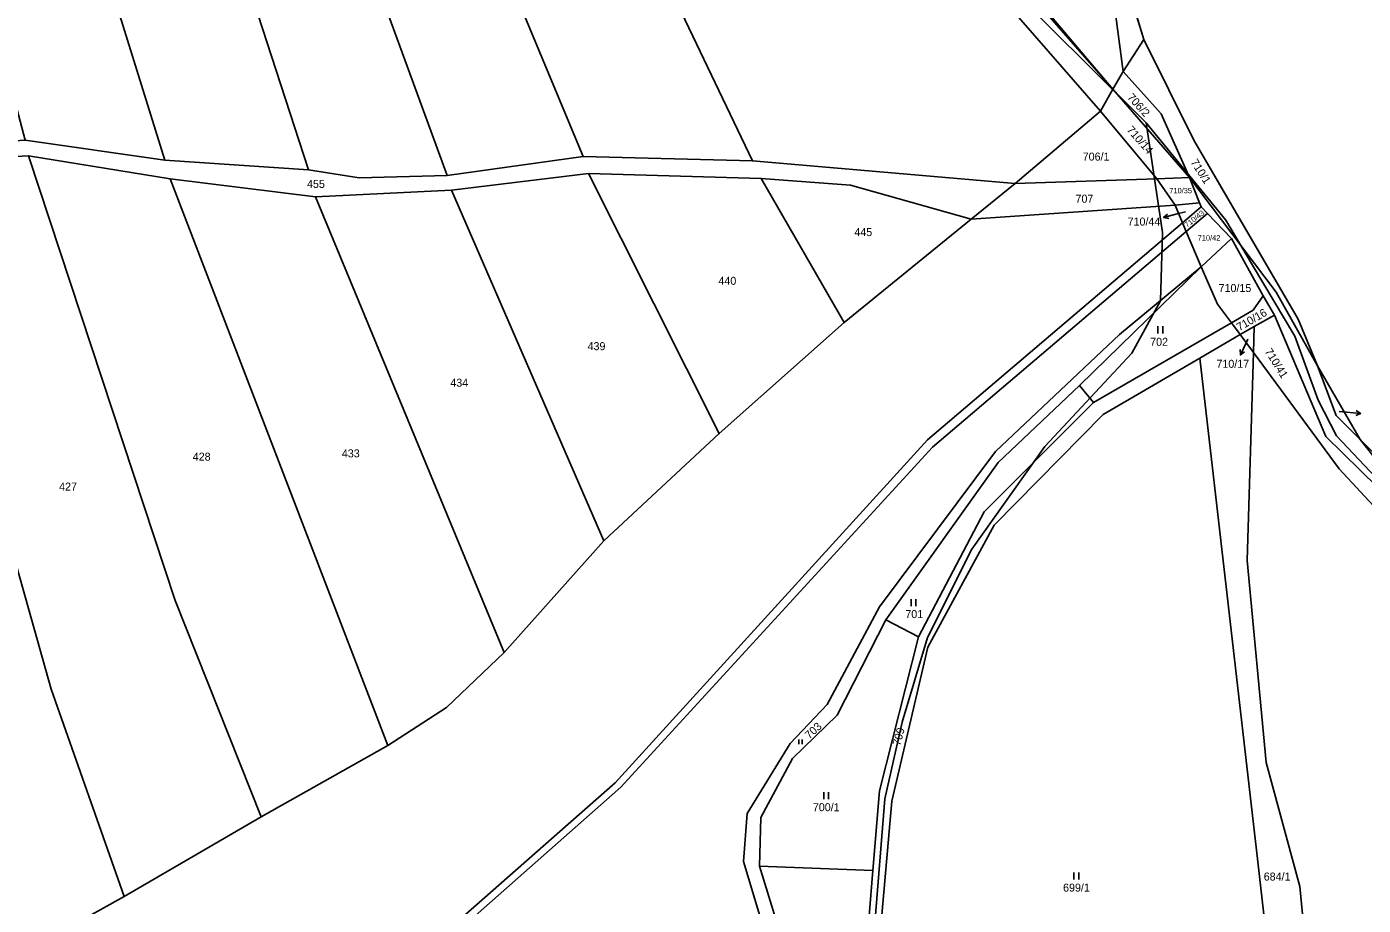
# Model space of a CAD drawing. Extents: x -590606 to -587796, y -1065936 to -1062515.
# Drawn here: x -590130 to -589846, y -1064536.2 to -1064349.5 of the extents above; entities that cross this region are included whole.
import ezdxf

# ---------------------------------------------------------------- set-up
doc = ezdxf.new("R2010")
doc.units = 0
for name, color, linetype in [('Cesty', 7, 'Continuous'), ('Parcela nároku', 7, 'Continuous'), ('Parcelní číslo', 7, 'Continuous'), ('Plocha pro ocenění', 7, 'Continuous'), ('Vnější obvod_ Studené', 7, 'Continuous'), ('Vrstva 30', 7, 'Continuous')]:
    doc.layers.add(name, color=color, linetype=linetype)

msp = doc.modelspace()

# ---------------------------------------------------------------- linework, layer by layer
at = {"layer": 'Cesty'}
for points in [[(-590216.42, -1064325.44), (-590129.27, -1064303.17), (-590056.17, -1064287.05), (-590041.95, -1064282.62), (-590009.62, -1064265.57), (-589994.11, -1064258.85), (-589983.83, -1064259.04), (-589970.7, -1064270), (-589941.39, -1064316.12), (-589927.11, -1064335.27), (-589904.53, -1064357.67), (-589892.17, -1064369.93), (-589888.72, -1064393.24), (-589889.13, -1064407.75), (-589895.21, -1064418.91), (-589913.67, -1064438.72), (-589929.2, -1064460.56), (-589938.62, -1064479.26), (-589944.01, -1064497.3), (-589947.72, -1064513.59), (-589949.88, -1064540.92)], [(-589892.17, -1064369.93), (-589875.26, -1064390.63), (-589869.59, -1064400.17), (-589860.61, -1064415.28), (-589855.62, -1064428.91), (-589851.76, -1064436.47), (-589835.09, -1064454.08), (-589818.14, -1064470.08), (-589809.98, -1064474.85), (-589789.91, -1064479.31), (-589769.84, -1064483.14), (-589746.37, -1064490.42), (-589728.15, -1064501.15), (-589708.7, -1064515.97), (-589695.75, -1064525.84), (-589673.94, -1064537.99), (-589648.4, -1064547.43), (-589623.17, -1064553.21), (-589602.26, -1064563.18), (-589592.55, -1064571.88), (-589566.17, -1064590.19), (-589543.56, -1064607.17)]]:
    msp.add_lwpolyline(points, dxfattribs=at)
at = {"layer": 'Parcela nároku'}
for points in [[(-589655.82, -1064541.47), (-589688.24, -1064525.96), (-589741.12, -1064488.48), (-589768.97, -1064479.77), (-589805.3, -1064473.64), (-589814.63, -1064469.28), (-589846.72, -1064437.22), (-589855.74, -1064421.61), (-589859.87, -1064411.67), (-589882.06, -1064373.61), (-589892.63, -1064352.24), (-589906.72, -1064306.48), (-589926.87, -1064283.27), (-589951.84, -1064263.05), (-589972.98, -1064252.89), (-589975.85, -1064251.08), (-589944.5, -1064222.75), (-589888.86, -1064196.21), (-589839.93, -1064178.91), (-589791, -1064136.14)], [(-589813.69, -1064476.1), (-589853.97, -1064436.59), (-589864.88, -1064410.84), (-589867.28, -1064406.68), (-589874.03, -1064394.54), (-589879.16, -1064389.2), (-589880.47, -1064387.83), (-589880.82, -1064386.97), (-589882.98, -1064381.6), (-589864.56, -1064405.91), (-589855.74, -1064421.61), (-589851.78, -1064432.15), (-589846.72, -1064437.22), (-589831.56, -1064456.33)]]:
    msp.add_lwpolyline(points, dxfattribs=at)
for points in [[(-589897.03, -1064359.06), (-589898.74, -1064346.25), (-589932.34, -1064314.81), (-589977.25, -1064253.94), (-589985.02, -1064255.71), (-589977.15, -1064259.13), (-589944.84, -1064307.79), (-589929.43, -1064328.26), (-589899.23, -1064362.79)], [(-589972.98, -1064252.89), (-589951.84, -1064263.05), (-589926.87, -1064283.27), (-589906.72, -1064306.48), (-589892.63, -1064352.24), (-589897.03, -1064359.06), (-589898.74, -1064346.25), (-589909.11, -1064307.7), (-589933.76, -1064281.49), (-589956.2, -1064265.03), (-589977.25, -1064253.94)], [(-589929.43, -1064328.26), (-589899.23, -1064362.79), (-589901.87, -1064367.49), (-589932.78, -1064331.95), (-589950.87, -1064308.38), (-589971.31, -1064277.38), (-589983.07, -1064265.62), (-589992.2, -1064262.59), (-590005.49, -1064266.82), (-590024.23, -1064276.77), (-590026.1, -1064272.84), (-590002.93, -1064259.89), (-589985.02, -1064255.71), (-589977.15, -1064259.13), (-589944.84, -1064307.79)], [(-589983.07, -1064265.62), (-589971.31, -1064277.38), (-589950.87, -1064308.38), (-589932.78, -1064331.95), (-589901.87, -1064367.49), (-589920.01, -1064382.84), (-589975.81, -1064378.06), (-590024.23, -1064276.77), (-590005.49, -1064266.82), (-589992.2, -1064262.59)], [(-589975.81, -1064378.06), (-590024.23, -1064276.77), (-590045.11, -1064287.87), (-590048.7, -1064288.55), (-590011.76, -1064377.13)], [(-590056.58, -1064290.05), (-590048.7, -1064288.55), (-590011.76, -1064377.13), (-590040.69, -1064381.12), (-590071.42, -1064297.09)], [(-590093.63, -1064307.62), (-590071.42, -1064297.09), (-590040.69, -1064381.12), (-590059.39, -1064381.65), (-590070.15, -1064379.94)], [(-590121.5, -1064310.91), (-590093.63, -1064307.62), (-590070.15, -1064379.94), (-590100.63, -1064377.89)], [(-590145.81, -1064314.9), (-590121.5, -1064310.91), (-590100.63, -1064377.89), (-590130.29, -1064373.64)], [(-589855.74, -1064421.61), (-589859.87, -1064411.67), (-589882.06, -1064373.61), (-589892.63, -1064352.24), (-589897.03, -1064359.06), (-589889, -1064368.04), (-589882.98, -1064381.6), (-589864.56, -1064405.91)], [(-589897.03, -1064359.06), (-589889, -1064368.04), (-589882.98, -1064381.6), (-589899.23, -1064362.79)], [(-589899.23, -1064362.79), (-589882.98, -1064381.6), (-589889.93, -1064381.84), (-589901.87, -1064367.49)], [(-590183.2, -1064369.34), (-590156.66, -1064375.29), (-590130.29, -1064373.64), (-590100.63, -1064377.89), (-590070.15, -1064379.94), (-590059.39, -1064381.65), (-590040.69, -1064381.12), (-590011.76, -1064377.13), (-589975.81, -1064378.06), (-589920.01, -1064382.84), (-589929.34, -1064390.39), (-589955.01, -1064383.19), (-589973.94, -1064381.77), (-590010.61, -1064380.74), (-590039.73, -1064384.26), (-590068.64, -1064385.67), (-590099.54, -1064381.89), (-590129.61, -1064376.95), (-590156.28, -1064378.4), (-590181.91, -1064373.1), (-590208.81, -1064367.46), (-590209.42, -1064364.07)], [(-589901.87, -1064367.49), (-589920.01, -1064382.84), (-589889.93, -1064381.84)], [(-590181.91, -1064373.1), (-590156.28, -1064378.4), (-590124.79, -1064490.26), (-590109.28, -1064534.33), (-590138.48, -1064550.51), (-590151.83, -1064503.77), (-590164.28, -1064447.03)], [(-590080.15, -1064517.38), (-590098.47, -1064471.44), (-590129.61, -1064376.95), (-590156.28, -1064378.4), (-590124.79, -1064490.26), (-590109.28, -1064534.33)], [(-590129.61, -1064376.95), (-590099.54, -1064381.89), (-590053.24, -1064502.26), (-590080.15, -1064517.38), (-590098.47, -1064471.44)], [(-590099.54, -1064381.89), (-590068.64, -1064385.67), (-590028.57, -1064482.51), (-590040.8, -1064494.15), (-590053.24, -1064502.26)], [(-590010.61, -1064380.74), (-589982.87, -1064435.99), (-590007.42, -1064458.77), (-590039.73, -1064384.26)], [(-589956.3, -1064412.36), (-589973.94, -1064381.77), (-590010.61, -1064380.74), (-589982.87, -1064435.99)], [(-589955.01, -1064383.19), (-589929.34, -1064390.39), (-589956.3, -1064412.36), (-589973.94, -1064381.77)], [(-589929.34, -1064390.39), (-589920.01, -1064382.84), (-589889.93, -1064381.84), (-589885.98, -1064387.45)], [(-589882.98, -1064381.6), (-589889.93, -1064381.84), (-589885.98, -1064387.45), (-589880.82, -1064386.97)], [(-590039.73, -1064384.26), (-590068.64, -1064385.67), (-590028.57, -1064482.51), (-590007.42, -1064458.77)], [(-590109.28, -1064534.33), (-590138.48, -1064550.51), (-590167.49, -1064566.1), (-590192.88, -1064580.25), (-590207.57, -1064588.44), (-590186.83, -1064622.39), (-590124.92, -1064590.99), (-590053.84, -1064553.16), (-590005.01, -1064510.14), (-589938.63, -1064437.29), (-589884.45, -1064391.22), (-589885.98, -1064387.45), (-589929.34, -1064390.39), (-589956.3, -1064412.36), (-589982.87, -1064435.99), (-590007.42, -1064458.77), (-590028.57, -1064482.51), (-590040.8, -1064494.15), (-590053.24, -1064502.26), (-590080.15, -1064517.38)], [(-589880.47, -1064387.83), (-589880.82, -1064386.97), (-589885.98, -1064387.45), (-589884.45, -1064391.22)], [(-589880.47, -1064387.83), (-589879.16, -1064389.2), (-589883.7, -1064393.06), (-589884.45, -1064391.22)], [(-589883.7, -1064393.06), (-589884.45, -1064391.22), (-589938.63, -1064437.29), (-590005.01, -1064510.14), (-590053.84, -1064553.16), (-590124.92, -1064590.99), (-590124.11, -1064592.68), (-590053.49, -1064555.03), (-590003.8, -1064511.09), (-589937.59, -1064438.88)], [(-589879.16, -1064389.2), (-589874.03, -1064394.54), (-589880.45, -1064400.57), (-589883.7, -1064393.06)], [(-589880.45, -1064400.57), (-589883.7, -1064393.06), (-589937.59, -1064438.88), (-590003.8, -1064511.09), (-590053.49, -1064555.03), (-590124.11, -1064592.68), (-590124.92, -1064590.99), (-590186.83, -1064622.39), (-590180.83, -1064633.16), (-590150.37, -1064687.39), (-590126.23, -1064681.5), (-590102.55, -1064674.49), (-590052.75, -1064654.76), (-590044.76, -1064645), (-590019.81, -1064609.39), (-590007.04, -1064591.31), (-589963.4, -1064574.51), (-589977.74, -1064526.91), (-589976.91, -1064516.68), (-589967.81, -1064501.82), (-589959.93, -1064493.53), (-589948.84, -1064472.81), (-589924.19, -1064439.77), (-589897.81, -1064414.93)], [(-589874.03, -1064394.54), (-589880.45, -1064400.57), (-589876.98, -1064408.49), (-589874.07, -1064412.43), (-589869.41, -1064409.73), (-589867.28, -1064406.68)], [(-589967.81, -1064501.82), (-589959.93, -1064493.53), (-589948.84, -1064472.81), (-589924.19, -1064439.77), (-589897.81, -1064414.93), (-589880.45, -1064400.57), (-589906.36, -1064425.79), (-589923.6, -1064442.15), (-589947.44, -1064475.52), (-589957.82, -1064495.76), (-589967.27, -1064504.99), (-589974.01, -1064517.56), (-589974.3, -1064527.88), (-589960.29, -1064573.39), (-589963.4, -1064574.51), (-589977.74, -1064526.91), (-589976.91, -1064516.68)], [(-589880.45, -1064400.57), (-589876.98, -1064408.49), (-589874.07, -1064412.43), (-589903.34, -1064429.38), (-589906.36, -1064425.79)], [(-589874.07, -1064412.43), (-589869.41, -1064409.73), (-589867.28, -1064406.68), (-589864.88, -1064410.84), (-589869.23, -1064413.25), (-589872.2, -1064414.96)], [(-589864.88, -1064410.84), (-589853.97, -1064436.59), (-589813.69, -1064476.1), (-589813.71, -1064476.97), (-589820.49, -1064473.59), (-589836.69, -1064459.05), (-589851.16, -1064443.43), (-589869.39, -1064418.76), (-589869.23, -1064413.25)], [(-589926.55, -1064452.59), (-589940.54, -1064479.13), (-589948.85, -1064511.85), (-589950.26, -1064528.81), (-589951.76, -1064548.03), (-589949.66, -1064571.06), (-589945.2, -1064570.03), (-589949.14, -1064547.91), (-589946.2, -1064514.04), (-589938.56, -1064481.34), (-589924.47, -1064455.4), (-589901.32, -1064431.9), (-589880.8, -1064419.92), (-589872.2, -1064414.96), (-589874.07, -1064412.43), (-589903.34, -1064429.38)], [(-589872.2, -1064414.96), (-589869.23, -1064413.25), (-589869.39, -1064418.76)], [(-589859.55, -1064532.21), (-589850.56, -1064625.55), (-589857.07, -1064626.89), (-589868.73, -1064524.47), (-589880.8, -1064419.92), (-589872.2, -1064414.96), (-589869.39, -1064418.76), (-589870.68, -1064462.95), (-589866.7, -1064505.87)], [(-589813.71, -1064476.97), (-589812.63, -1064521.48), (-589808.25, -1064610.3), (-589808.34, -1064612.83), (-589850.56, -1064625.55), (-589859.55, -1064532.21), (-589866.7, -1064505.87), (-589870.68, -1064462.95), (-589869.39, -1064418.76), (-589851.16, -1064443.43), (-589836.69, -1064459.05), (-589820.49, -1064473.59)], [(-589857.07, -1064626.89), (-589868.73, -1064524.47), (-589880.8, -1064419.92), (-589901.32, -1064431.9), (-589924.47, -1064455.4), (-589938.56, -1064481.34), (-589946.2, -1064514.04), (-589949.14, -1064547.91), (-589945.2, -1064570.03), (-589931.51, -1064618.95), (-589922.06, -1064639.58)], [(-589846.72, -1064437.22), (-589855.74, -1064421.61), (-589851.78, -1064432.15)], [(-589947.44, -1064475.52), (-589923.6, -1064442.15), (-589906.36, -1064425.79), (-589903.34, -1064429.38), (-589926.55, -1064452.59), (-589940.54, -1064479.13)], [(-589814.63, -1064469.28), (-589846.72, -1064437.22), (-589831.56, -1064456.33)], [(-589967.27, -1064504.99), (-589957.82, -1064495.76), (-589947.44, -1064475.52), (-589940.54, -1064479.13), (-589948.85, -1064511.85), (-589950.26, -1064528.81), (-589974.3, -1064527.88), (-589974.01, -1064517.56)], [(-589951.76, -1064548.03), (-589949.66, -1064571.06), (-589960.29, -1064573.39), (-589974.3, -1064527.88), (-589950.26, -1064528.81)]]:
    msp.add_lwpolyline(points, close=True, dxfattribs=at)
at = {"layer": 'Parcelní číslo'}
for p, q in [((-589885.57, -1064389.32), (-589888.47, -1064390.08)), ((-589883.78, -1064388.86), (-589885.57, -1064389.32)), ((-589870.86, -1064416.56), (-589872.16, -1064419.26)), ((-589870.54, -1064415.9), (-589870.86, -1064416.56)), ((-589851.17, -1064431.28), (-589849.59, -1064431.42)), ((-589849.59, -1064431.42), (-589846.6, -1064431.69))]:
    msp.add_line(p, q, dxfattribs=at)
for points in [[(-589887.38, -1064390.31), (-589888.47, -1064390.08), (-589887.63, -1064389.34)], [(-589871.28, -1064418.58), (-589872.16, -1064419.26), (-589872.18, -1064418.14)], [(-589847.55, -1064431.1), (-589846.6, -1064431.69), (-589847.64, -1064432.1)]]:
    msp.add_lwpolyline(points, dxfattribs=at)
at = {"layer": 'Plocha pro ocenění'}
msp.add_lwpolyline([(-589972.98, -1064252.89), (-589977.25, -1064253.94), (-589985.02, -1064255.71), (-589977.15, -1064259.13), (-589937.14, -1064318.02), (-589899.23, -1064362.79), (-589897.03, -1064359.06), (-589892.63, -1064352.24)], dxfattribs=at)
at = {"layer": 'Vnější obvod_ Studené'}
for p, q in [((-589892.63, -1064352.24), (-589906.72, -1064306.48)), ((-589882.06, -1064373.61), (-589892.63, -1064352.24)), ((-589870.96, -1064392.64), (-589882.06, -1064373.61)), ((-589859.87, -1064411.67), (-589870.96, -1064392.64)), ((-589855.74, -1064421.61), (-589859.87, -1064411.67)), ((-589846.72, -1064437.22), (-589855.74, -1064421.61)), ((-589814.63, -1064469.28), (-589846.72, -1064437.22))]:
    msp.add_line(p, q, dxfattribs=at)
at = {"layer": 'Vrstva 30'}
for p, q in [((-589889.68, -1064413.18), (-589889.68, -1064414.68)), ((-589888.66, -1064414.68), (-589888.66, -1064413.18)), ((-589942.09, -1064471.12), (-589942.09, -1064472.62)), ((-589941.07, -1064472.62), (-589941.07, -1064471.12)), ((-589965.93, -1064500.94), (-589965.93, -1064501.94)), ((-589965.24, -1064501.94), (-589965.24, -1064500.94)), ((-589960.66, -1064512.13), (-589960.66, -1064513.63)), ((-589959.64, -1064513.63), (-589959.64, -1064512.13)), ((-589907.51, -1064529.21), (-589907.51, -1064530.71)), ((-589906.48, -1064530.71), (-589906.48, -1064529.21))]:
    msp.add_line(p, q, dxfattribs=at)

# ---------------------------------------------------------------- texts
at = {"layer": 'Parcela nároku'}
for s, height, rotation, p in [('706/2', 1.7, 312.3388, (-589896.3, -1064364.65)), ('710/14', 1.7, 311.4553, (-589896.4, -1064371.55)), ('710/1', 1.7, 302.576, (-589882.8, -1064378.33)), ('710/43', 1.14, 37.213, (-589883.5, -1064392.24)), ('710/16', 1.7, 29.9816, (-589872.35, -1064414.25)), ('710/41', 1.7, 301.7632, (-589867.03, -1064418.5)), ('703', 1.7, 42.6281, (-589963.72, -1064500.97)), ('709', 1.7, 74.6808, (-589944.43, -1064502.4))]:
    msp.add_text(s, height=height, rotation=rotation, dxfattribs=at).set_placement(p)
for s, height, p in [('706/1', 1.7, (-589905.65, -1064377.98)), ('455', 1.7, (-590070.44, -1064383.79)), ('707', 1.7, (-589907.18, -1064386.92)), ('710/35', 1.14, (-589887.25, -1064384.93)), ('710/44', 0.1, (-589883.98, -1064388.86)), ('445', 1.7, (-589954.16, -1064394.02)), ('710/42', 1.14, (-589881.22, -1064394.96)), ('440', 1.7, (-589983.04, -1064404.37)), ('710/15', 1.7, (-589876.78, -1064405.9)), ('439', 1.7, (-590010.84, -1064418.25)), ('702', 1.7, (-589891.32, -1064417.33)), ('710/17', 0.1, (-589870.72, -1064415.9)), ('434', 1.7, (-590040, -1064426.01)), ('710/26', 0.1, (-589851.37, -1064431.28)), ('433', 1.7, (-590063.04, -1064441.03)), ('428', 1.7, (-590094.72, -1064441.73)), ('427', 1.7, (-590123.11, -1064448.08)), ('701', 1.7, (-589943.33, -1064475.17)), ('700/1', 1.7, (-589962.98, -1064516.2)), ('684/1', 1.7, (-589867.19, -1064530.93)), ('699/1', 1.7, (-589909.82, -1064533.28))]:
    msp.add_text(s, height=height, dxfattribs=at).set_placement(p)
at = {"layer": 'Parcelní číslo'}
for s, p in [('710/44', (-589896.11, -1064391.78)), ('710/17', (-589877.24, -1064422))]:
    msp.add_text(s, height=1.7, dxfattribs=at).set_placement(p)

doc.saveas('drawing.dxf')
